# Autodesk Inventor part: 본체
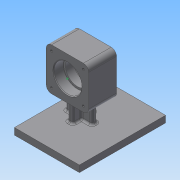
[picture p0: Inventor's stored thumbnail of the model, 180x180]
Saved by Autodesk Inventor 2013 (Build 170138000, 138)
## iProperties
Created: 2020-11
Part Number: 본체
Material: Generic
Document SubType Name: Modeling
Designer: Administrator
Density: 1 g/cm^3
Author: Administrator
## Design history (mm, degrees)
sketch "스케치1"
  geometry: 1 further point
sketch "스케치2"
  geometry: L1 (32, -32)-(-32, -32); L2 (-32, -32)-(-32, 32); L3 (-32, 32)-(32, 32); L4 (32, 32)-(32, -32); L5 (32, -32)-(-32, 32); L6 (-32, -32)-(32, 32); 1 further point
  constraints: 12 end point, 2 midpoint, 2 parallel, 1 horizontal, 1 perpendicular
  dimensions: "d0" = 64 distance of L2.end L3.end; "d2" = 64 distance of L3.end L1.start
extrude "돌출1" new body sketch "스케치2" distance "d3" = 42; taper "d4" = 0 deg
sketch "스케치3"
  geometry: C1 r 21 at (0, 0); 1 further point
  constraints: 1 centre point, 1 coincident
  dimensions: "d5" = 42 diameter of C1
extrude "돌출2" cut sketch "스케치3" distance "d7" = 15; taper "d8" = 0 deg
sketch "스케치4"
  geometry: C1 r 21 at (0, 0); 1 further point
  constraints: 1 centre point, 1 coincident
  dimensions: "d9" = 42 diameter of C1
extrude "돌출3" cut sketch "스케치4" distance "d11" = 15; taper "d12" = 0 deg
sketch "스케치5"
  geometry: C1 r 18 at (0, 0); 1 further point
  constraints: 1 centre point, 1 coincident
  dimensions: "d13" = 36 diameter of C1
extrude "돌출4" cut sketch "스케치5" distance "d15" = 15; taper "d16" = 0 deg
fillet "모깎기1" dims "d17" = 0.3
fillet "모깎기2" dims "d18" = 8
sketch "스케치6"
  geometry: 5 further points
  dimensions: "d19" = 48 distance of point (24, 24) point (-24, 24); "d21" = 48 distance of point (24, -24) point (-24, -24); "d22" = 48 distance of point (-24, -24) point (-24, 24); "d23" = 48 distance of point (24, -24) point (24, 24); "d24" = 24 horizontal distance of point (24, 24) point (0, 0); "d25" = 24 horizontal distance of point (24, -24) point (0, 0); "d26" = 24 horizontal distance of point (-24, -24) point (0, 0); "d27" = 24 horizontal distance of point (24, -24) point (0, 0)
hole "구멍1" sketch "스케치6" at (-24, 24), (24, 24), (24, -24), (-24, -24) diameter "d28" = 3.242; stored, may be unused: countersink angle "d32" = 90 deg, drill point angle "d34" = 118 deg; dims "d29" = 8, "d30" = 4, "d31" = 2, "d33" = 10
sketch "스케치7"
  geometry: 5 further points
  dimensions: "d35" = 48 distance of point (24, 24) point (-24, 24); "d37" = 48 distance of point (24, -24) point (-24, -24); "d38" = 48 distance of point (-24, -24) point (-24, 24); "d39" = 48 distance of point (24, -24) point (24, 24); "d40" = 24 horizontal distance of point (-24, 24) point (0, 0); "d41" = 24 horizontal distance of point (-24, -24) point (0, 0); "d42" = 24 horizontal distance of point (-24, -24) point (0, 0); "d43" = 24 horizontal distance of point (24, 24) point (0, 0)
hole "구멍2" sketch "스케치7" at (24, -24), (-24, -24), (24, 24), (-24, 24) diameter "d44" = 3.242; stored, may be unused: countersink angle "d48" = 90 deg, drill point angle "d50" = 118 deg; dims "d45" = 8, "d46" = 4, "d47" = 2, "d49" = 10
chamfer "모따기1" distance "d51" = 1; stored, may be unused: second distance "d52" = 2, angle "d53" = 45 deg
node "작업 평면1"
sketch "스케치8"
  geometry: L1 (-36, -44)-(62, -44); L2 (62, -44)-(62, 86); L3 (62, 86)-(-36, 86); L4 (-36, 86)-(-36, -44); L5 (-36, -44)-(62, 86); L6 (62, -44)-(-36, 86); L7 (-24, 0)-(24, 0) reference; 2 further points
  constraints: 12 end point, 2 midpoint, 2 parallel, 1 horizontal, 1 perpendicular
  dimensions: "d55" = 130 distance of L1.end L2.end; "d57" = 98 distance of L1.start L1.end; "d58" = 62 distance from line of point (0, 0) L2; "d60" = 44 distance between parallel lines of L1 L7
extrude "돌출5" join sketch "스케치8" distance "d61" = 10; taper "d62" = 0 deg
sketch "스케치9"
  geometry: L1 (20, 25)-(20, 17); L2 (20, 17)-(4, 17); L3 (4, 17)-(4, 4); L4 (4, 4)-(-4, 4); L5 (-4, 4)-(-4, 17); L6 (-4, 17)-(-20, 17); L7 (-20, 17)-(-20, 25); L8 (-20, 25)-(-4, 25); L9 (-4, 25)-(-4, 38); L10 (-4, 38)-(4, 38); L11 (4, 38)-(4, 25); L12 (4, 25)-(20, 25); L13 (20, 21)-(-20, 21); L14 (0, 38)-(0, 4); L15 (24, 42)-(-24, 42) reference; L16 (-32, 0)-(-32, 42) reference; 1 further point
  constraints: 28 end point, 7 parallel, 4 midpoint, 2 collinear, 2 perpendicular, 1 vertical
  dimensions: "d74" = 17 distance between parallel lines of L4 L13; "d76" = 17 distance from line of L14.start L13; "d77" = 20 distance between parallel lines of L7 L14; "d78" = 20 distance between parallel lines of L1 L14; "d79" = 8 distance of L3.end L4.end; "d80" = 8 distance of L1.start L1.end; "d81" = 8 distance of L9.end L10.end; "d82" = 8 distance of L6.end L7.end; "d83" = 4 distance between parallel lines of L15 L10; "d84" = 12 distance between parallel lines of L16 L7
extrude "돌출6" join sketch "스케치9" stored distance "d85" = 10; taper "d86" = 0 deg
fillet "모깎기3" dims "d87" = 3
fillet "모깎기4" dims "d88" = 3
fillet "모깎기5" dims "d89" = 3
node "솔리드1"
